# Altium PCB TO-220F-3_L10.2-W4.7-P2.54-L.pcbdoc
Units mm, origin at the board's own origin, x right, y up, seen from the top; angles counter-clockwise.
Board outline 23.44 x 18.27 mm, 2 copper layers (Top Layer, Bottom Layer), stack 0 mm thick; 1 components, 0 nets, 3 pads, 0 vias.
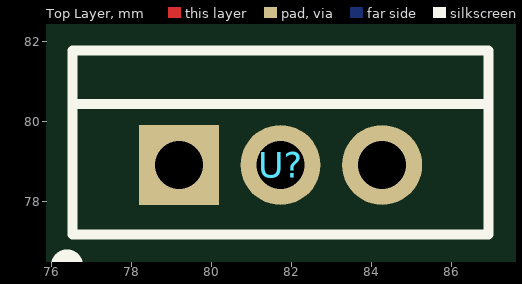
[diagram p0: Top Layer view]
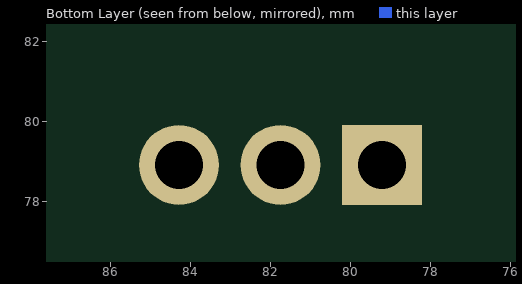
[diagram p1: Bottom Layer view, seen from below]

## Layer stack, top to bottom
Top Layer: signal copper (thickness not stored)
Bottom Layer: signal copper (thickness not stored)

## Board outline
93.287,69.85 69.85,69.85 69.85,88.12 93.287,88.12

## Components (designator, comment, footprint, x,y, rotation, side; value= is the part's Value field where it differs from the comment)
U? "" TO-220F-3_L10.2-W4.7-P2.54-L 81.737,78.91 r0 top

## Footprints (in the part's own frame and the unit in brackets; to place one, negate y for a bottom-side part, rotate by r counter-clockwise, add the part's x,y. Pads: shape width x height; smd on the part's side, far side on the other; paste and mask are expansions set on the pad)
TO-220F-3_L10.2-W4.7-P2.54-L [mm]
  rect 2x2 hole 1.2: 1(-2.54,0)
  round 2 hole 1.2: 2(0,0) 3(2.54,0)
  silkscreen extent -5.54,-2.71 5.2,2.86

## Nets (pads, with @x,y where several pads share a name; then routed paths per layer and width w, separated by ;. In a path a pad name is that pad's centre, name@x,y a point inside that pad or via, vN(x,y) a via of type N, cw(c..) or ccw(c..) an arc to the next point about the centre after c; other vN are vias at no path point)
pads on no net: U?.1 U?.2 U?.3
